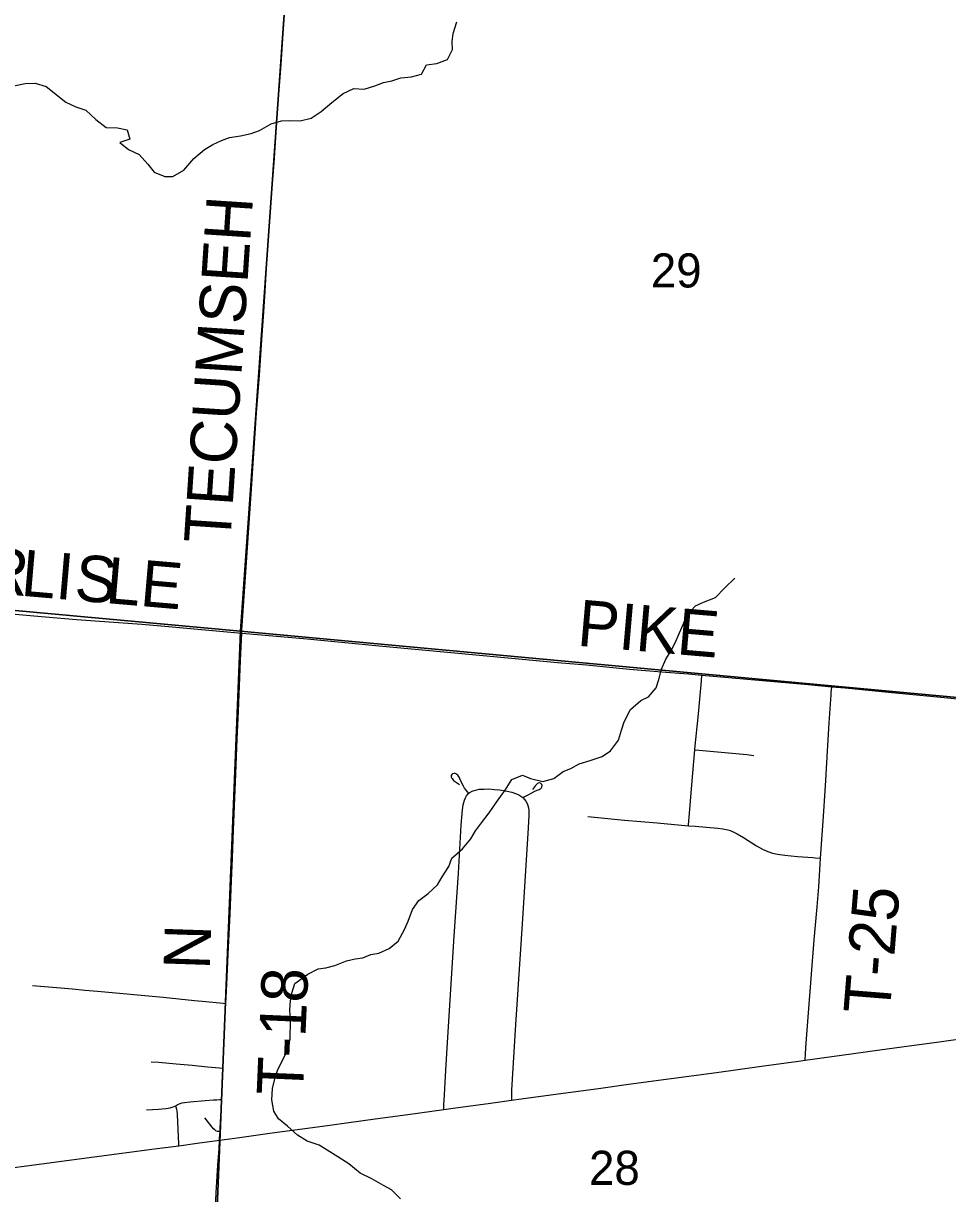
# Model space of a CAD drawing. Extents: x 831 to 1552, y 430 to 870.
# Drawn here: x 1343.42 to 1366.09, y 727.92 to 756.64 of the extents above; entities that cross this region are included whole.
import ezdxf

# ---------------------------------------------------------------- set-up
doc = ezdxf.new("R2010")
doc.units = 0
for name, color, linetype in [('GM_X_Corporation', 7, 'Continuous'), ('GM_X_County_Road', 7, 'Continuous'), ('GM_X_County_Road_Text', 7, 'Continuous'), ('GM_X_Minor_River', 7, 'Continuous'), ('GM_X_Section_Text', 7, 'Continuous'), ('GM_X_State_Route', 7, 'Continuous'), ('GM_X_Township_Road', 7, 'Continuous'), ('GM_X_Township_Road_Text', 7, 'Continuous'), ('GM_X_US_Route', 7, 'Continuous')]:
    doc.layers.add(name, color=color, linetype=linetype)

msp = doc.modelspace()

# ---------------------------------------------------------------- linework, layer by layer
at = {"layer": 'GM_X_Corporation'}
for points in [[(1331.382, 763.355), (1350.153, 761.603), (1348.747, 741.721), (1329.567, 743.48)], [(1350.153, 761.603), (1370.37, 759.881), (1368.637, 739.883), (1348.747, 741.721)], [(1329.567, 743.48), (1348.747, 741.721), (1347.89, 720.702), (1327.468, 722.912)], [(1348.747, 741.721), (1368.637, 739.883), (1366.951, 719.126), (1347.89, 720.702)]]:
    msp.add_lwpolyline(points, close=True, dxfattribs=at)
at = {"layer": 'GM_X_County_Road'}
for points in [[(1339.477, 742.716), (1339.486, 742.706), (1339.53, 742.663), (1339.576, 742.624), (1339.625, 742.588), (1339.677, 742.556), (1339.73, 742.528), (1339.786, 742.504), (1339.844, 742.484), (1339.938, 742.461), (1340.043, 742.442), (1340.247, 742.417), (1340.891, 742.358), (1341.938, 742.256), (1342.866, 742.172), (1343.671, 742.101), (1344.723, 742.01), (1346.323, 741.894), (1346.979, 741.841), (1347.971, 741.752), (1348.778, 741.677)], [(1348.778, 741.677), (1348.97, 741.66), (1350.379, 741.533), (1352.148, 741.363), (1354.087, 741.183), (1355.218, 741.08), (1356.521, 740.959), (1357.235, 740.895), (1358.292, 740.796), (1359.18, 740.72), (1359.734, 740.675), (1360.067, 740.645)], [(1360.067, 740.645), (1361.826, 740.488), (1362.579, 740.421), (1363.252, 740.36)], [(1363.252, 740.36), (1363.58, 740.331), (1364.722, 740.223), (1365.843, 740.115), (1366.995, 739.995), (1367.727, 739.918), (1368.5, 739.832), (1368.658, 739.814)]]:
    msp.add_lwpolyline(points, dxfattribs=at)
at = {"layer": 'GM_X_Minor_River'}
for points in [[(1343.184, 755.113), (1343.458, 755.163), (1343.709, 755.175), (1343.974, 755.096), (1344.463, 754.71), (1344.704, 754.593), (1344.947, 754.515), (1345.194, 754.284), (1345.45, 754.083), (1345.724, 754.08), (1345.966, 754.031), (1346.032, 753.802), (1345.787, 753.722), (1345.998, 753.544), (1346.262, 753.427), (1346.472, 753.189), (1346.629, 752.989), (1346.886, 752.888), (1347.084, 752.885), (1347.351, 753.042), (1347.598, 753.328), (1347.859, 753.545), (1348.066, 753.672), (1348.28, 753.768), (1348.478, 753.842), (1348.745, 753.884), (1349.004, 753.942), (1349.21, 754.016), (1349.501, 754.179), (1349.752, 754.252), (1349.942, 754.258), (1350.208, 754.247), (1350.482, 754.312), (1350.72, 754.477), (1350.989, 754.701), (1351.265, 754.919), (1351.525, 755.045), (1351.775, 755.027), (1352.042, 755.107), (1352.256, 755.188), (1352.454, 755.232), (1352.675, 755.305), (1352.941, 755.332), (1353.185, 755.398), (1353.31, 755.624), (1353.561, 755.659), (1353.82, 755.755), (1353.945, 755.997), (1353.94, 756.195), (1353.965, 756.392), (1354.052, 756.68)], [(1350.379, 729.208), (1350.145, 729.355), (1349.897, 729.578), (1349.679, 729.756), (1349.56, 729.947), (1349.51, 730.221), (1349.529, 730.502), (1349.585, 730.737), (1349.664, 730.964), (1349.797, 731.236), (1349.906, 731.455), (1349.962, 731.713), (1349.968, 732.169), (1349.956, 732.427), (1349.974, 732.655), (1350.007, 732.844), (1350.078, 733.079), (1350.4, 733.303), (1350.652, 733.437), (1350.842, 733.465), (1351.056, 733.523), (1351.346, 733.634), (1351.559, 733.685), (1351.749, 733.705), (1351.94, 733.786), (1352.138, 733.822), (1352.39, 733.933), (1352.613, 734.12), (1352.769, 734.4), (1352.855, 734.604), (1352.965, 734.891), (1353.119, 735.117), (1353.349, 735.289), (1353.58, 735.499), (1353.696, 735.696), (1353.852, 735.952), (1353.93, 736.156), (1354.191, 736.381), (1354.399, 736.63), (1354.508, 736.826), (1354.655, 737.022), (1354.848, 737.27), (1355.026, 737.526), (1355.235, 737.82), (1355.398, 738.084), (1355.665, 738.188), (1355.861, 738.109), (1356.164, 738.037), (1356.431, 738.11), (1356.661, 738.282), (1356.852, 738.356), (1357.051, 738.468), (1357.325, 738.548), (1357.615, 738.651), (1357.822, 738.785), (1358.015, 739.049), (1358.095, 739.299), (1358.158, 739.496), (1358.314, 739.805), (1358.567, 740.023), (1358.758, 740.112), (1358.943, 740.338), (1359.007, 740.542), (1359.071, 740.792), (1359.18, 741.034), (1359.304, 741.238), (1359.405, 741.442), (1359.515, 741.684), (1359.601, 741.888), (1359.695, 742.115), (1359.911, 742.348), (1360.102, 742.437), (1360.399, 742.548), (1360.623, 742.781), (1360.869, 743.029)], [(1352.671, 727.79), (1352.453, 728.013), (1352.25, 728.122), (1351.963, 728.285), (1351.684, 728.425), (1351.405, 728.649), (1351.134, 728.827), (1350.87, 728.989), (1350.674, 729.113), (1350.379, 729.208)]]:
    msp.add_lwpolyline(points, dxfattribs=at)
at = {"layer": 'GM_X_State_Route'}
msp.add_lwpolyline([(1348.11, 727.007), (1348.151, 727.938), (1348.192, 728.621), (1348.22, 729.016), (1348.231, 729.233)], dxfattribs=at)
at = {"layer": 'GM_X_Township_Road'}
for points in [[(1348.778, 741.677), (1348.781, 741.748), (1348.872, 743.175), (1349.011, 745.222), (1349.062, 745.966), (1349.141, 747.082), (1349.209, 748.012), (1349.279, 748.999), (1349.308, 749.439), (1349.35, 750.058), (1349.37, 750.368), (1349.393, 750.74), (1349.442, 751.484), (1349.498, 752.291), (1349.567, 753.221), (1349.656, 754.461), (1349.688, 754.895), (1349.739, 755.639), (1349.801, 756.507), (1349.846, 757.189)], [(1348.386, 732.585), (1348.41, 733.052), (1348.44, 733.797), (1348.488, 734.79), (1348.521, 735.598), (1348.546, 736.157), (1348.574, 736.84), (1348.619, 738.021), (1348.666, 739.077), (1348.695, 739.76), (1348.747, 741.003), (1348.778, 741.677)], [(1359.893, 738.815), (1359.895, 738.828), (1359.98, 739.698), (1360.055, 740.507), (1360.067, 740.645)], [(1362.976, 736.15), (1363.038, 737.06), (1363.094, 737.928), (1363.155, 738.92), (1363.187, 739.479), (1363.233, 740.161), (1363.239, 740.223), (1363.252, 740.36)], [(1359.736, 736.95), (1359.745, 737.086), (1359.749, 737.148), (1359.82, 737.957), (1359.893, 738.815)], [(1359.893, 738.815), (1359.999, 738.805), (1361.164, 738.695), (1361.338, 738.677)], [(1354.343, 737.742), (1354.281, 737.821), (1354.244, 737.868), (1354.213, 737.919), (1354.161, 738.028), (1354.111, 738.138), (1354.077, 738.188), (1354.053, 738.208), (1354.034, 738.221), (1354.008, 738.229), (1353.983, 738.233), (1353.949, 738.224), (1353.926, 738.21), (1353.914, 738.185), (1353.914, 738.147), (1353.924, 738.124), (1353.935, 738.106), (1353.951, 738.082), (1353.972, 738.061), (1354.071, 737.991), (1354.116, 737.96)], [(1354.343, 737.742), (1354.373, 737.768), (1354.425, 737.797), (1354.48, 737.818), (1354.539, 737.833), (1354.599, 737.843), (1354.66, 737.849), (1354.721, 737.851), (1354.841, 737.853), (1354.98, 737.839)], [(1354.98, 737.839), (1355.102, 737.827), (1355.285, 737.801), (1355.404, 737.772), (1355.519, 737.731), (1355.574, 737.706), (1355.626, 737.675), (1355.673, 737.639)], [(1355.673, 737.639), (1355.769, 737.688), (1355.82, 737.715), (1355.878, 737.745), (1355.986, 737.802), (1356.045, 737.829), (1356.072, 737.842), (1356.099, 737.856), (1356.114, 737.866), (1356.127, 737.878), (1356.135, 737.894), (1356.141, 737.911), (1356.142, 737.925), (1356.143, 737.94), (1356.136, 737.965), (1356.115, 737.989), (1356.101, 737.996), (1356.086, 738), (1356.051, 737.996), (1356.028, 737.984), (1355.985, 737.938), (1355.909, 737.838)], [(1353.731, 729.982), (1353.737, 730.139), (1353.74, 730.201), (1353.782, 730.947), (1353.827, 731.63), (1353.99, 734.236), (1354.091, 735.789), (1354.159, 736.967), (1354.188, 737.339), (1354.206, 737.46), (1354.221, 737.519), (1354.24, 737.577), (1354.263, 737.632), (1354.292, 737.685), (1354.328, 737.73), (1354.343, 737.742)], [(1355.673, 737.639), (1355.715, 737.597), (1355.749, 737.549), (1355.774, 737.499), (1355.794, 737.446), (1355.809, 737.388), (1355.815, 737.328), (1355.818, 737.206), (1355.805, 736.897), (1355.735, 735.845), (1355.653, 734.544), (1355.602, 733.801), (1355.49, 732.067), (1355.391, 730.46), (1355.39, 730.291), (1355.39, 730.214)], [(1357.264, 737.177), (1357.511, 737.148), (1358.164, 737.089), (1358.968, 737.02), (1359.736, 736.95)], [(1359.736, 736.95), (1359.897, 736.935), (1360.454, 736.889), (1360.577, 736.872), (1360.699, 736.846), (1360.758, 736.829), (1360.816, 736.807), (1360.928, 736.752), (1361.088, 736.657), (1361.402, 736.456), (1361.566, 736.366), (1361.679, 736.316), (1361.797, 736.276), (1361.918, 736.249), (1362.103, 736.225), (1362.412, 736.198), (1362.784, 736.169), (1362.846, 736.163), (1362.976, 736.15)], [(1362.599, 731.196), (1362.607, 731.362), (1362.62, 731.611), (1362.683, 732.354), (1362.822, 734.151), (1362.892, 734.955), (1362.933, 735.449), (1362.967, 736.007), (1362.976, 736.15)], [(1343.641, 733.031), (1343.938, 733.007), (1344.625, 732.944), (1344.927, 732.914), (1345.236, 732.889), (1346.847, 732.742), (1347.616, 732.663), (1347.894, 732.633), (1348.323, 732.591), (1348.386, 732.585)], [(1348.312, 730.997), (1348.338, 731.5), (1348.372, 732.307), (1348.386, 732.585)], [(1346.554, 731.155), (1346.739, 731.145), (1347.17, 731.107), (1347.557, 731.07), (1347.938, 731.033), (1348.227, 731.005), (1348.312, 730.997)], [(1348.242, 729.441), (1348.246, 729.52), (1348.269, 729.967), (1348.278, 730.226), (1348.284, 730.366), (1348.293, 730.631), (1348.312, 730.997)], [(1347.157, 730.076), (1347.193, 730.096), (1347.226, 730.115), (1347.264, 730.132), (1347.316, 730.148), (1347.37, 730.158), (1347.512, 730.175), (1347.874, 730.205), (1348.081, 730.222), (1348.167, 730.226), (1348.227, 730.229), (1348.26, 730.227), (1348.278, 730.226)], [(1346.435, 729.975), (1346.735, 729.992), (1346.913, 730.007), (1346.971, 730.016), (1347.021, 730.028), (1347.091, 730.049), (1347.136, 730.066), (1347.157, 730.076)], [(1347.232, 729.097), (1347.23, 729.144), (1347.222, 729.315), (1347.195, 729.866), (1347.188, 729.951), (1347.183, 729.987), (1347.167, 730.041), (1347.157, 730.076)], [(1348.242, 729.441), (1348.218, 729.444), (1348.177, 729.448), (1348.139, 729.463), (1348.113, 729.482), (1348.085, 729.512), (1347.866, 729.78)], [(1348.231, 729.233), (1348.233, 729.269), (1348.242, 729.441)]]:
    msp.add_lwpolyline(points, dxfattribs=at)
at = {"layer": 'GM_X_US_Route'}
for points in [[(1362.599, 731.196), (1363.486, 731.318), (1364.428, 731.446), (1365.152, 731.544), (1365.829, 731.64), (1366.752, 731.768), (1367.01, 731.804)], [(1348.231, 729.233), (1348.602, 729.284), (1349.525, 729.409), (1350.756, 729.578), (1352.049, 729.755), (1352.849, 729.861), (1353.731, 729.982), (1354.018, 730.022), (1354.822, 730.134), (1355.39, 730.214), (1355.628, 730.247), (1356.665, 730.384), (1357.526, 730.503), (1358.265, 730.605), (1359.312, 730.746), (1360.42, 730.894), (1361.528, 731.045), (1362.434, 731.174), (1362.599, 731.196)], [(1327.897, 726.561), (1329.462, 726.76), (1330.817, 726.937), (1331.679, 727.052), (1332.603, 727.174), (1334.144, 727.374), (1335.915, 727.605), (1336.839, 727.726), (1338.525, 727.95), (1339.611, 728.089), (1340.596, 728.22), (1342.438, 728.463), (1342.506, 728.472), (1343.368, 728.587), (1345.154, 728.821), (1346.632, 729.017), (1347.232, 729.097), (1347.679, 729.157), (1348.231, 729.233)]]:
    msp.add_lwpolyline(points, dxfattribs=at)

# ---------------------------------------------------------------- texts
at = {"layer": 'GM_X_County_Road_Text'}
for s, height, rotation, p in [('R', 1.136, 355.0838, (1342.406, 742.677)), ('L', 1.136, 355.0826, (1343.336, 742.597)), ('I', 1.136, 355.0868, (1344.183, 742.524)), ('S', 1.136, 355.0863, (1344.648, 742.484)), ('L', 1.136, 355.0826, (1345.412, 742.418)), ('E', 1.136, 355.0853, (1346.259, 742.345)), ('PIKE', 1.1364, 355.0831, (1356.985, 741.37))]:
    msp.add_text(s, height=height, rotation=rotation, dxfattribs=at).set_placement(p)
at = {"layer": 'GM_X_Section_Text'}
for s, p in [('29', (1358.812, 750.16)), ('28', (1357.296, 728.135))]:
    msp.add_text(s, height=0.8371, rotation=0, dxfattribs=at).set_placement(p)
at = {"layer": 'GM_X_Township_Road_Text'}
for s, height, rotation, p in [('TECUMSEH', 1.1364, 86.211, (1348.49, 743.851)), ('T-25', 1.1364, 85.4133, (1364.67, 732.301)), ('N', 1.136, 88.0882, (1347.99, 733.407)), ('T-18', 1.1364, 87.5347, (1350.275, 730.316))]:
    msp.add_text(s, height=height, rotation=rotation, dxfattribs=at).set_placement(p)

doc.saveas('drawing.dxf')
